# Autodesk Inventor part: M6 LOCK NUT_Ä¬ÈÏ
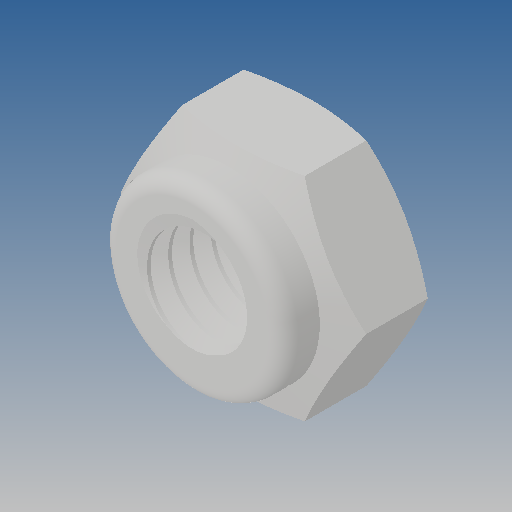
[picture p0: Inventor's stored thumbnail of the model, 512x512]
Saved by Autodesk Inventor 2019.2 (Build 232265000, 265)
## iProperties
Created: 2010-06
Part Number: M6 LOCK NUT_Ä¬ÈÏ
Material: Ogólny
Document SubType Name: Modeling
Designer: CADENGINEERING4
Density: 1 g/cm^3
Appearance: Domyślna
Author: CADENGINEERING4
Revision Number: ÈÎºÎ
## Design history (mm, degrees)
feature "NONE"
node "Bryła1"
